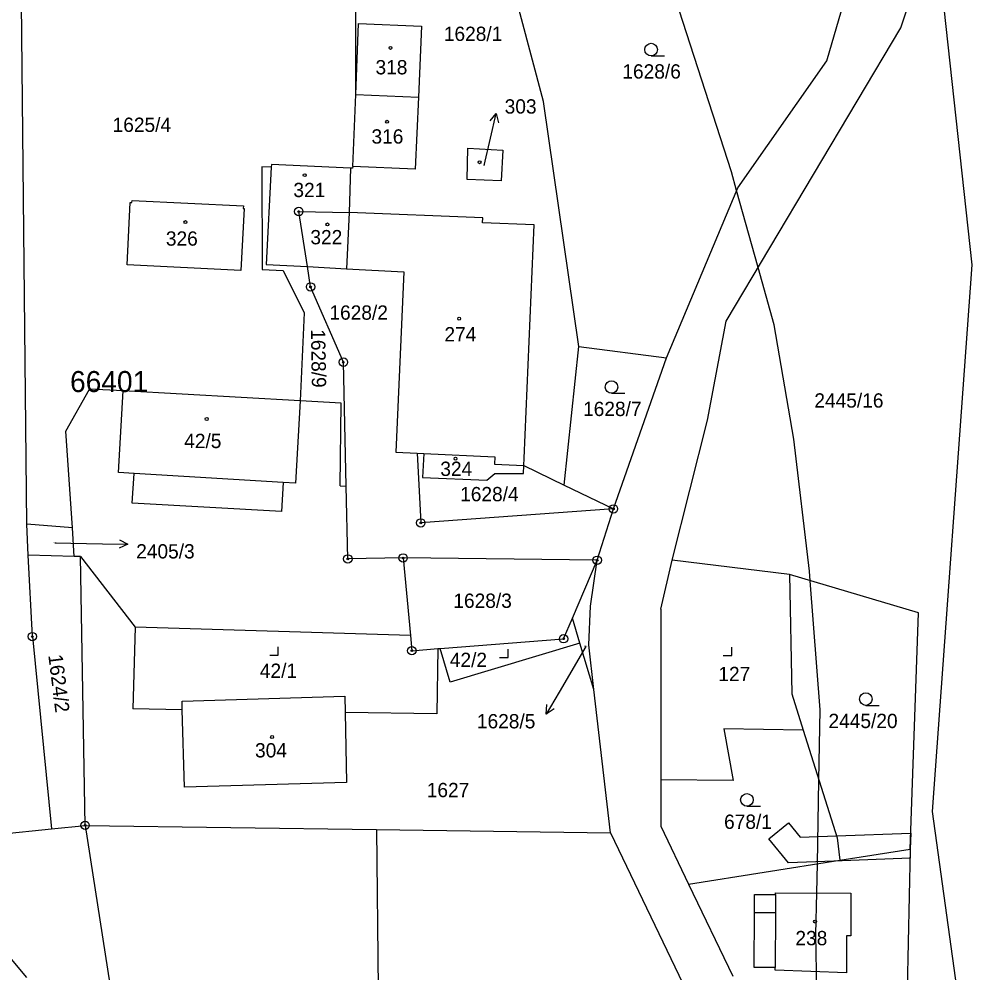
# Model space of a CAD drawing. Extents: x -546762 to -540209, y -1046851 to -1035694.
# Drawn here: x -542720.2 to -542606.9, y -1039670.1 to -1039556.7 of the extents above; entities that cross this region are included whole.
import ezdxf

# ---------------------------------------------------------------- set-up
doc = ezdxf.new("R2010")
doc.units = 0
for name, color, linetype in [('Vrstva 1', 7, 'Continuous'), ('Vrstva 16', 7, 'Continuous'), ('Vrstva 18', 7, 'Continuous'), ('Vrstva 19', 7, 'Continuous'), ('Vrstva 24', 7, 'Continuous'), ('Vrstva 25', 7, 'Continuous'), ('Vrstva 3', 7, 'Continuous'), ('Vrstva 30', 7, 'Continuous'), ('Vrstva 37', 7, 'Continuous'), ('Vrstva 4', 7, 'Continuous'), ('Vrstva 52', 7, 'Continuous'), ('Vrstva 53', 7, 'Continuous')]:
    doc.layers.add(name, color=color, linetype=linetype)

msp = doc.modelspace()

# ---------------------------------------------------------------- linework, layer by layer
at = {"layer": 'Vrstva 1'}
for p, q in [((-542680.18, -1039565.65), (-542680.19, -1039551.14)), ((-542707.37, -1039585.87), (-542707, -1039578.47)), ((-542707, -1039578.47), (-542706.79, -1039578.48)), ((-542706.79, -1039578.48), (-542706.78, -1039578.23)), ((-542706.78, -1039578.23), (-542693.55, -1039578.88)), ((-542693.45, -1039579.18), (-542693.83, -1039586.58)), ((-542693.55, -1039578.88), (-542693.57, -1039579.18)), ((-542693.57, -1039579.18), (-542693.45, -1039579.18)), ((-542693.83, -1039586.58), (-542707.37, -1039585.87)), ((-542712.36, -1039652.51), (-542712.89, -1039620.57)), ((-542718.63, -1039630.07), (-542716.34, -1039652.92)), ((-542712.36, -1039652.51), (-542677.71, -1039653))]:
    msp.add_line(p, q, dxfattribs=at)
for points in [[(-542719.28, -1039616.7), (-542720.1, -1039535.34)], [(-542657.86, -1039566.46), (-542664.56, -1039541.27)], [(-542624.18, -1039561.65), (-542621.62, -1039552.75)], [(-542615.4, -1039557.71), (-542614.37, -1039554.62)], [(-542610.29, -1039555.38), (-542606.95, -1039585.89)], [(-542680.18, -1039565.65), (-542679.85, -1039557.2), (-542672.37, -1039557.51), (-542672.75, -1039565.95)], [(-542636.15, -1039592.59), (-542615.4, -1039557.71)], [(-542634.79, -1039576.73), (-542624.18, -1039561.65)], [(-542680.54, -1039574.22), (-542680.18, -1039565.65)], [(-542680.18, -1039565.65), (-542672.75, -1039565.95)], [(-542672.75, -1039565.95), (-542673.12, -1039574.52)], [(-542653.66, -1039595.59), (-542657.86, -1039566.46)], [(-542666.93, -1039575.73), (-542666.85, -1039572.03)], [(-542666.85, -1039572.03), (-542662.7, -1039572.26)], [(-542662.7, -1039572.26), (-542662.89, -1039575.91)], [(-542690.23, -1039574.26), (-542691.35, -1039574.24)], [(-542691.35, -1039574.24), (-542691.32, -1039586.45)], [(-542690.23, -1039574.26), (-542690.85, -1039585.84), (-542685.94, -1039586.1)], [(-542680.82, -1039574.4), (-542690.22, -1039573.98), (-542690.23, -1039574.26)], [(-542680.82, -1039574.4), (-542680.98, -1039579.68)], [(-542680.59, -1039574.4), (-542680.82, -1039574.4)], [(-542680.54, -1039574.22), (-542680.59, -1039574.4)], [(-542673.12, -1039574.52), (-542680.54, -1039574.22)], [(-542662.89, -1039575.91), (-542666.93, -1039575.73)], [(-542643.24, -1039596.94), (-542634.79, -1039576.73)], [(-542685.94, -1039586.1), (-542686.97, -1039579.55)], [(-542686.97, -1039579.55), (-542680.98, -1039579.68)], [(-542680.98, -1039579.68), (-542681.3, -1039586.35)], [(-542665.08, -1039580.29), (-542680.98, -1039579.68)], [(-542665.11, -1039580.89), (-542665.08, -1039580.29)], [(-542659, -1039581.15), (-542665.11, -1039580.89)], [(-542660.19, -1039608.85), (-542659, -1039581.15)], [(-542606.95, -1039585.89), (-542611.68, -1039650.85)], [(-542691.32, -1039586.45), (-542688.82, -1039586.56)], [(-542688.82, -1039586.56), (-542686.31, -1039591.58)], [(-542685.94, -1039586.1), (-542681.3, -1039586.35)], [(-542685.56, -1039588.51), (-542685.94, -1039586.1)], [(-542681.3, -1039586.35), (-542674.48, -1039586.71)], [(-542674.48, -1039586.71), (-542675.41, -1039608.16)], [(-542681.66, -1039597.46), (-542685.56, -1039588.51)], [(-542686.31, -1039591.58), (-542686.8, -1039602.05)], [(-542638.38, -1039604.34), (-542636.15, -1039592.59)], [(-542655.4, -1039612.08), (-542653.66, -1039595.59)], [(-542653.66, -1039595.59), (-542643.24, -1039596.94)], [(-542649.56, -1039614.9), (-542643.24, -1039596.94)], [(-542681.33, -1039612.19), (-542681.66, -1039597.46)], [(-542714.64, -1039605.65), (-542711.82, -1039600.66)], [(-542707.83, -1039600.88), (-542711.82, -1039600.66)], [(-542706.51, -1039610.68), (-542708.38, -1039610.57), (-542707.83, -1039600.88)], [(-542686.8, -1039602.05), (-542707.83, -1039600.88)], [(-542686.8, -1039602.05), (-542687.37, -1039611.83), (-542688.81, -1039611.74)], [(-542681.91, -1039602.32), (-542686.8, -1039602.05)], [(-542682.04, -1039612.15), (-542681.91, -1039602.32)], [(-542642.56, -1039620.99), (-542638.38, -1039604.34)], [(-542713.86, -1039617.16), (-542714.64, -1039605.65)], [(-542675.41, -1039608.16), (-542672.87, -1039608.28)], [(-542672.87, -1039608.28), (-542672.46, -1039616.56)], [(-542672.87, -1039608.28), (-542672.1, -1039608.31)], [(-542672.1, -1039608.31), (-542672.26, -1039611.17), (-542664.6, -1039611.49), (-542663.66, -1039610.7), (-542660.27, -1039610.7), (-542660.23, -1039609.75)], [(-542672.1, -1039608.31), (-542663.65, -1039608.7)], [(-542663.65, -1039608.7), (-542663.69, -1039609.58)], [(-542663.69, -1039609.58), (-542660.23, -1039609.75)], [(-542660.23, -1039609.75), (-542660.19, -1039608.85)], [(-542660.23, -1039609.75), (-542655.4, -1039612.08)], [(-542688.81, -1039611.74), (-542689.01, -1039615.21), (-542706.76, -1039614.22), (-542706.51, -1039610.68)], [(-542682.04, -1039612.15), (-542681.33, -1039612.19)], [(-542681.13, -1039620.84), (-542681.33, -1039612.19)], [(-542655.4, -1039612.08), (-542649.56, -1039614.9)], [(-542649.56, -1039614.9), (-542672.46, -1039616.56)], [(-542651.49, -1039621), (-542649.56, -1039614.9)], [(-542713.86, -1039617.16), (-542719.28, -1039616.7)], [(-542719.11, -1039620.4), (-542719.28, -1039616.7)], [(-542713.67, -1039620.55), (-542713.86, -1039617.16)], [(-542718.63, -1039630.07), (-542719.11, -1039620.4)], [(-542713.67, -1039620.55), (-542719.11, -1039620.4)], [(-542712.89, -1039620.57), (-542713.67, -1039620.55)], [(-542712.89, -1039620.57), (-542706.39, -1039628.95)], [(-542674.56, -1039620.73), (-542681.13, -1039620.84)], [(-542651.49, -1039621), (-542674.56, -1039620.73)], [(-542674.56, -1039620.73), (-542673.69, -1039629.93)], [(-542654.44, -1039627.9), (-542651.49, -1039621)], [(-542652.3, -1039626.46), (-542651.49, -1039621)], [(-542643.92, -1039626.83), (-542642.56, -1039620.99)], [(-542628.64, -1039622.7), (-542642.56, -1039620.99)], [(-542628.64, -1039622.7), (-542628.34, -1039636.87)], [(-542613.31, -1039627.26), (-542628.64, -1039622.7)], [(-542652.49, -1039631.06), (-542652.3, -1039626.46)], [(-542655.48, -1039630.33), (-542654.44, -1039627.9)], [(-542653.55, -1039630.84), (-542654.44, -1039627.9)], [(-542643.92, -1039626.83), (-542643.94, -1039647.09)], [(-542614.29, -1039655.34), (-542613.31, -1039627.26)], [(-542706.39, -1039628.95), (-542706.68, -1039638.68)], [(-542673.69, -1039629.93), (-542673.52, -1039631.75)], [(-542670.17, -1039631.48), (-542655.48, -1039630.33)], [(-542653.55, -1039630.84), (-542668.95, -1039635.51)], [(-542651.88, -1039636.35), (-542653.55, -1039630.84)], [(-542651.88, -1039636.35), (-542652.49, -1039631.06)], [(-542673.52, -1039631.75), (-542670.43, -1039631.5)], [(-542670.43, -1039631.5), (-542670.55, -1039639.25)], [(-542670.43, -1039631.5), (-542670.17, -1039631.48)], [(-542668.95, -1039635.51), (-542670.17, -1039631.48)], [(-542649.92, -1039653.39), (-542651.88, -1039636.35)], [(-542628.34, -1039636.87), (-542626.99, -1039641.19)], [(-542700.83, -1039637.74), (-542681.48, -1039637.15)], [(-542700.81, -1039638.77), (-542700.83, -1039637.74)], [(-542681.48, -1039637.15), (-542681.44, -1039639.08)], [(-542700.81, -1039638.77), (-542706.68, -1039638.68)], [(-542700.55, -1039647.97), (-542700.81, -1039638.77)], [(-542681.44, -1039639.08), (-542681.28, -1039647.41)], [(-542670.55, -1039639.25), (-542681.44, -1039639.08)], [(-542626.99, -1039641.19), (-542636.44, -1039641.03)], [(-542636.44, -1039641.03), (-542635.34, -1039647.16)], [(-542626.99, -1039641.19), (-542622.98, -1039654)], [(-542635.34, -1039647.16), (-542643.94, -1039647.09)], [(-542643.94, -1039647.09), (-542643.94, -1039652.59)], [(-542681.28, -1039647.41), (-542700.55, -1039647.97)], [(-542611.68, -1039650.85), (-542608.44, -1039674.34)], [(-542716.34, -1039652.92), (-542712.36, -1039652.51)], [(-542712.36, -1039652.51), (-542705.86, -1039694.34)], [(-542643.94, -1039652.59), (-542640.62, -1039659.5)], [(-542722.54, -1039653.57), (-542716.34, -1039652.92)], [(-542677.71, -1039653), (-542649.92, -1039653.39)], [(-542677.71, -1039653), (-542677.33, -1039690.89)], [(-542649.92, -1039653.39), (-542640.84, -1039672.31)], [(-542622.98, -1039654), (-542622.66, -1039656.66)], [(-542622.66, -1039656.66), (-542614.29, -1039655.34)], [(-542614.29, -1039655.34), (-542614.78, -1039677.52)], [(-542640.62, -1039659.5), (-542622.66, -1039656.66)], [(-542640.62, -1039659.5), (-542635.36, -1039670.45)], [(-542632.8, -1039662.91), (-542632.79, -1039660.71)], [(-542632.79, -1039660.71), (-542630.29, -1039660.72)], [(-542630.29, -1039660.72), (-542630.29, -1039660.52)], [(-542630.29, -1039660.52), (-542621.34, -1039660.56)], [(-542621.34, -1039660.56), (-542621.36, -1039665.63)], [(-542632.83, -1039669.41), (-542632.8, -1039662.91)], [(-542621.86, -1039665.63), (-542621.87, -1039670.03)], [(-542621.36, -1039665.63), (-542621.86, -1039665.63)], [(-542630.33, -1039669.42), (-542632.83, -1039669.41)], [(-542630.33, -1039669.72), (-542630.33, -1039669.42)], [(-542621.87, -1039670.03), (-542630.33, -1039669.72)]]:
    msp.add_lwpolyline(points, dxfattribs=at)
at = {"layer": 'Vrstva 16'}
for p, q in [((-542664.17, -1039570.83), (-542663.49, -1039567.91)), ((-542710.29, -1039619.04), (-542707.29, -1039619.09)), ((-542656.03, -1039636.69), (-542657.54, -1039639.28))]:
    msp.add_line(p, q, dxfattribs=at)
for points in [[(-542664.2, -1039568.77), (-542663.49, -1039567.91), (-542663.23, -1039569)], [(-542664.94, -1039574.1), (-542664.17, -1039570.83)], [(-542708.28, -1039618.57), (-542707.29, -1039619.09), (-542708.3, -1039619.57)], [(-542715.95, -1039618.95), (-542710.29, -1039619.04)], [(-542652.85, -1039631.26), (-542656.03, -1039636.69)], [(-542656.61, -1039638.67), (-542657.54, -1039639.28), (-542657.47, -1039638.16)]]:
    msp.add_lwpolyline(points, dxfattribs=at)
at = {"layer": 'Vrstva 24'}
for centre, radius in [((-542686.97, -1039579.55), 0.5), ((-542686.97, -1039579.55), 0.1), ((-542685.56, -1039588.51), 0.5), ((-542685.56, -1039588.51), 0.1), ((-542681.66, -1039597.46), 0.5), ((-542681.66, -1039597.46), 0.1), ((-542649.56, -1039614.9), 0.5), ((-542649.56, -1039614.9), 0.1), ((-542672.46, -1039616.56), 0.5), ((-542672.46, -1039616.56), 0.1), ((-542681.13, -1039620.84), 0.5), ((-542681.13, -1039620.84), 0.1), ((-542674.56, -1039620.73), 0.5), ((-542674.56, -1039620.73), 0.1), ((-542651.49, -1039621), 0.5), ((-542651.49, -1039621), 0.1), ((-542718.63, -1039630.07), 0.5), ((-542718.63, -1039630.07), 0.1), ((-542655.48, -1039630.33), 0.5), ((-542673.52, -1039631.75), 0.5), ((-542655.48, -1039630.33), 0.1), ((-542673.52, -1039631.75), 0.1), ((-542712.36, -1039652.51), 0.5), ((-542712.36, -1039652.51), 0.1)]:
    msp.add_circle(centre, radius, dxfattribs=at)
at = {"layer": 'Vrstva 25'}
for p, q in [((-542645.08, -1039561.05), (-542643.48, -1039561.05)), ((-542649.79, -1039601.16), (-542648.19, -1039601.16)), ((-542619.56, -1039638.25), (-542617.96, -1039638.25)), ((-542633.7, -1039650.23), (-542632.1, -1039650.23))]:
    msp.add_line(p, q, dxfattribs=at)
for points in [[(-542690.41, -1039632.28), (-542689.41, -1039632.28), (-542689.41, -1039631.28)], [(-542636.5, -1039632.34), (-542635.5, -1039632.34), (-542635.5, -1039631.34)], [(-542663.09, -1039632.56), (-542662.09, -1039632.56), (-542662.09, -1039631.56)]]:
    msp.add_lwpolyline(points, dxfattribs=at)
for centre, radius in [((-542645.08, -1039560.3), 0.75), ((-542676.06, -1039560.1), 0.175), ((-542676.47, -1039568.88), 0.175), ((-542665.47, -1039573.7), 0.175), ((-542686.26, -1039575.23), 0.175), ((-542700.44, -1039580.81), 0.175), ((-542683.56, -1039581.08), 0.175), ((-542667.9, -1039592.29), 0.175), ((-542649.79, -1039600.41), 0.75), ((-542697.91, -1039604.21), 0.175), ((-542668.33, -1039608.93), 0.175), ((-542619.56, -1039637.5), 0.75), ((-542690.13, -1039642.01), 0.175), ((-542633.7, -1039649.48), 0.75), ((-542625.59, -1039663.95), 0.175)]:
    msp.add_circle(centre, radius, dxfattribs=at)
at = {"layer": 'Vrstva 3'}
for points in [[(-542680.18, -1039565.65), (-542679.85, -1039557.2), (-542672.37, -1039557.51), (-542672.75, -1039565.95)], [(-542680.54, -1039574.22), (-542680.18, -1039565.65)], [(-542680.18, -1039565.65), (-542672.75, -1039565.95)], [(-542680.18, -1039565.65), (-542672.75, -1039565.95)], [(-542672.75, -1039565.95), (-542673.12, -1039574.52)], [(-542666.93, -1039575.73), (-542666.85, -1039572.03)], [(-542666.85, -1039572.03), (-542662.7, -1039572.26)], [(-542662.7, -1039572.26), (-542662.89, -1039575.91)], [(-542690.23, -1039574.26), (-542690.85, -1039585.84), (-542685.94, -1039586.1)], [(-542680.82, -1039574.4), (-542690.22, -1039573.98), (-542690.23, -1039574.26)], [(-542680.82, -1039574.4), (-542680.98, -1039579.68)], [(-542673.12, -1039574.52), (-542680.54, -1039574.22)], [(-542662.89, -1039575.91), (-542666.93, -1039575.73)], [(-542707.37, -1039585.87), (-542707, -1039578.47)], [(-542707, -1039578.47), (-542706.79, -1039578.48)], [(-542706.79, -1039578.48), (-542706.78, -1039578.23)], [(-542706.78, -1039578.23), (-542693.55, -1039578.88)], [(-542693.45, -1039579.18), (-542693.83, -1039586.58)], [(-542693.55, -1039578.88), (-542693.57, -1039579.18)], [(-542693.57, -1039579.18), (-542693.45, -1039579.18)], [(-542665.08, -1039580.29), (-542680.98, -1039579.68)], [(-542665.11, -1039580.89), (-542665.08, -1039580.29)], [(-542659, -1039581.15), (-542665.11, -1039580.89)], [(-542660.19, -1039608.85), (-542659, -1039581.15)], [(-542693.83, -1039586.58), (-542707.37, -1039585.87)], [(-542685.94, -1039586.1), (-542681.3, -1039586.35)], [(-542681.3, -1039586.35), (-542674.48, -1039586.71)], [(-542674.48, -1039586.71), (-542675.41, -1039608.16)], [(-542706.51, -1039610.68), (-542708.38, -1039610.57), (-542707.83, -1039600.88)], [(-542686.8, -1039602.05), (-542707.83, -1039600.88)], [(-542686.8, -1039602.05), (-542687.37, -1039611.83), (-542688.81, -1039611.74)], [(-542675.41, -1039608.16), (-542672.87, -1039608.28)], [(-542672.87, -1039608.28), (-542672.1, -1039608.31)], [(-542672.1, -1039608.31), (-542672.26, -1039611.17), (-542664.6, -1039611.49), (-542663.66, -1039610.7), (-542660.27, -1039610.7), (-542660.23, -1039609.75)], [(-542660.23, -1039609.75), (-542660.19, -1039608.85)], [(-542688.81, -1039611.74), (-542706.51, -1039610.68)], [(-542700.83, -1039637.74), (-542681.48, -1039637.15)], [(-542700.81, -1039638.77), (-542700.83, -1039637.74)], [(-542681.48, -1039637.15), (-542681.44, -1039639.08)], [(-542700.55, -1039647.97), (-542700.81, -1039638.77)], [(-542681.44, -1039639.08), (-542681.28, -1039647.41)], [(-542681.28, -1039647.41), (-542700.55, -1039647.97)], [(-542630.29, -1039660.72), (-542630.3, -1039662.92)], [(-542630.29, -1039660.72), (-542630.29, -1039660.52)], [(-542630.29, -1039660.52), (-542621.34, -1039660.56)], [(-542621.34, -1039660.56), (-542621.36, -1039665.63)], [(-542630.3, -1039662.92), (-542630.33, -1039669.42)], [(-542621.86, -1039665.63), (-542621.87, -1039670.03)], [(-542621.36, -1039665.63), (-542621.86, -1039665.63)], [(-542630.33, -1039669.72), (-542630.33, -1039669.42)], [(-542621.87, -1039670.03), (-542630.33, -1039669.72)]]:
    msp.add_lwpolyline(points, dxfattribs=at)
at = {"layer": 'Vrstva 30'}
msp.add_lwpolyline([(-542623.06, -1039653.76), (-542614.22, -1039653.42), (-542614.29, -1039655.34), (-542614.31, -1039656.43), (-542623.38, -1039656.77), (-542628.74, -1039656.98), (-542631.07, -1039654.11), (-542628.74, -1039652.22), (-542627.36, -1039653.92), (-542623.06, -1039653.76)], dxfattribs=at)
at = {"layer": 'Vrstva 37'}
for centre in [(-542676.06, -1039560.1), (-542676.47, -1039568.88), (-542665.47, -1039573.7), (-542700.44, -1039580.81), (-542667.9, -1039592.29), (-542697.91, -1039604.21), (-542690.13, -1039642.01), (-542625.59, -1039663.95)]:
    msp.add_circle(centre, 0.175, dxfattribs=at)
at = {"layer": 'Vrstva 4'}
for points in [[(-542688.81, -1039611.74), (-542706.51, -1039610.68)], [(-542673.69, -1039629.93), (-542706.39, -1039628.95)], [(-542630.29, -1039660.72), (-542630.3, -1039662.92)], [(-542630.3, -1039662.92), (-542632.8, -1039662.91)], [(-542630.3, -1039662.92), (-542630.33, -1039669.42)]]:
    msp.add_lwpolyline(points, dxfattribs=at)
at = {"layer": 'Vrstva 52'}
for points in [[(-542625.24, -1039682.75), (-542625.43, -1039669.9), (-542625.49, -1039665.46), (-542625.39, -1039660.54), (-542625.32, -1039657.08), (-542625.13, -1039647.13), (-542624.97, -1039638.78), (-542626.18, -1039623.43), (-542626.27, -1039622.31), (-542628.1, -1039606.61), (-542630.45, -1039593.01), (-542632.35, -1039586.21), (-542634.92, -1039577.04), (-542635.54, -1039574.82), (-542644.42, -1039547.36)], [(-542721.94, -1039667.45), (-542719.31, -1039670.58)]]:
    msp.add_lwpolyline(points, dxfattribs=at)

# ---------------------------------------------------------------- texts
at = {"layer": 'Vrstva 16'}
for s, p in [('303', (-542662.49, -1039567.91)), ('2405/3', (-542706.29, -1039620.79)), ('1628/5', (-542665.79, -1039640.98))]:
    msp.add_text(s, height=1.7, dxfattribs=at).set_placement(p)
at = {"layer": 'Vrstva 18'}
for s, height, p in [('1628/1', 1.7, (-542669.72, -1039559.28)), ('1628/6', 1.7, (-542648.5, -1039563.75)), ('1625/4', 1.7, (-542709.09, -1039570.09)), ('1628/2', 1.7, (-542683.32, -1039592.41)), ('2445/16', 1.7, (-542625.68, -1039602.86)), ('1628/7', 1.7, (-542653.17, -1039603.86)), ('1628/4', 1.7, (-542667.78, -1039613.99)), ('2405/3', 0.1, (-542716.18, -1039618.95)), ('1628/3', 1.7, (-542668.59, -1039626.66)), ('1628/5', 0.1, (-542653.06, -1039631.26)), ('2445/20', 1.7, (-542624, -1039640.95)), ('1627', 1.7, (-542671.75, -1039649.16)), ('678/1', 1.7, (-542636.41, -1039652.93))]:
    msp.add_text(s, height=height, dxfattribs=at).set_placement(p)
for s, rotation, p in [('1628/9', 270.9759, (-542685.52, -1039593.55)), ('1624/2', 277.125, (-542716.74, -1039632.29))]:
    msp.add_text(s, height=1.7, rotation=rotation, dxfattribs=at).set_placement(p)
at = {"layer": 'Vrstva 19'}
for s, height, p in [('318', 1.7, (-542677.84, -1039563.25)), ('316', 1.7, (-542678.32, -1039571.48)), ('303', 0.1, (-542665.05, -1039574.1)), ('321', 1.7, (-542687.6, -1039577.84)), ('326', 1.7, (-542702.76, -1039583.61)), ('322', 1.7, (-542685.58, -1039583.45)), ('274', 1.7, (-542669.65, -1039594.99)), ('42/5', 1.7, (-542700.58, -1039607.67)), ('324', 1.7, (-542670.14, -1039610.98)), ('42/2', 1.7, (-542669.01, -1039633.69)), ('42/1', 1.7, (-542691.59, -1039634.98)), ('127', 1.7, (-542637.09, -1039635.37)), ('304', 1.7, (-542692.16, -1039644.44)), ('238', 1.7, (-542627.93, -1039666.76))]:
    msp.add_text(s, height=height, dxfattribs=at).set_placement(p)
at = {"layer": 'Vrstva 53'}
msp.add_text('66401', height=2.5, dxfattribs=at).set_placement((-542714.15, -1039601.01))

doc.saveas('drawing.dxf')
